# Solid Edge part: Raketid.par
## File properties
Author: Egon 815
Template: Normal.par
Last saved by: Egon 815
Revision: 4
Application: Solid Edge
Accuracy: 0,990
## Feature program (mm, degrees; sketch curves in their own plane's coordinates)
sketch for "ExtrudedProtrusion_1" plane through (0, 0, 5032.5774) normal (0, 0, 1) x-axis (1, 0, 0)
  circle centre (-4129.348, 8677.0977) radius 1000
extrude "ExtrudedProtrusion_1" add finite 11672.7216 along +normal
pattern "unnamed Pattern 1" of "ExtrudedProtrusion_1"
extrude "unnamed Protrusion 1" add finite 11672.7216
extrude "unnamed Protrusion 2" add finite 11672.7216
extrude "unnamed Protrusion 3" add finite 11672.7216
extrude "unnamed Protrusion 4" add finite 11672.7216
extrude "unnamed Protrusion 5" add finite 11672.7216
extrude "unnamed Protrusion 6" add finite 11672.7216
extrude "unnamed Protrusion 7" add finite 11672.7216
extrude "unnamed Protrusion 8" add finite 11672.7216
extrude "unnamed Protrusion 9" add finite 11672.7216
extrude "unnamed Protrusion 10" add finite 11672.7216
extrude "unnamed Protrusion 11" add finite 11672.7216
extrude "unnamed Protrusion 12" add finite 11672.7216
extrude "unnamed Protrusion 13" add finite 11672.7216
extrude "unnamed Protrusion 14" add finite 11672.7216
extrude "unnamed Protrusion 15" add finite 11672.7216
extrude "unnamed Protrusion 16" add finite 11672.7216
extrude "unnamed Protrusion 17" add finite 11672.7216
extrude "unnamed Protrusion 18" add finite 11672.7216
extrude "unnamed Protrusion 19" add finite 11672.7216
extrude "unnamed Protrusion 20" add finite 11672.7216
extrude "unnamed Protrusion 21" add finite 11672.7216
extrude "unnamed Protrusion 22" add finite 11672.7216
extrude "unnamed Protrusion 23" add finite 11672.7216
fillet "Round_2" radius 1000
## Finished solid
Body 1: solid body, 72 faces, 48 edges, 0 vertices, 24 separate solids.
  Faces by surface: cylinder 24, plane 24, sphere 24
  Edges by curve: circle 48
Bounding box of the edges (mm; curved faces can reach further): 10341.762 x 22192.390 x 10672.722, from (-5129.348, 7677.0977, 5032.5774) to (5212.414, 29869.4874, 15705.2991).
Cylindrical faces by radius (mm): R1000 x24
Spherical faces by radius (mm): R1000 x24
Planar faces by outward normal: -z 24
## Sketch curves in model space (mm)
circle centre (-4129.348, 8677.0977, 5032.5774) radius 1000
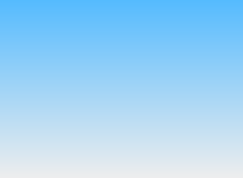
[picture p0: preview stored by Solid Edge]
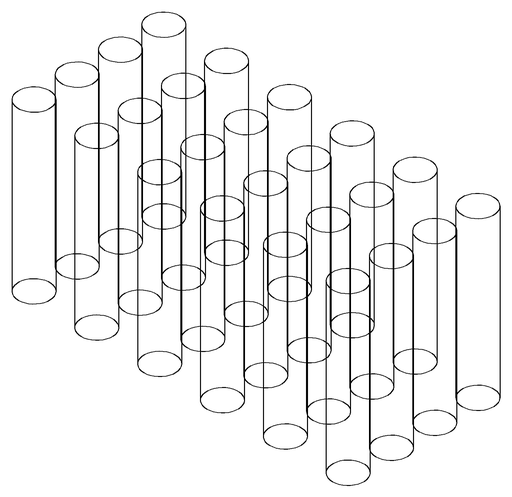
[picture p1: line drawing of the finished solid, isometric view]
